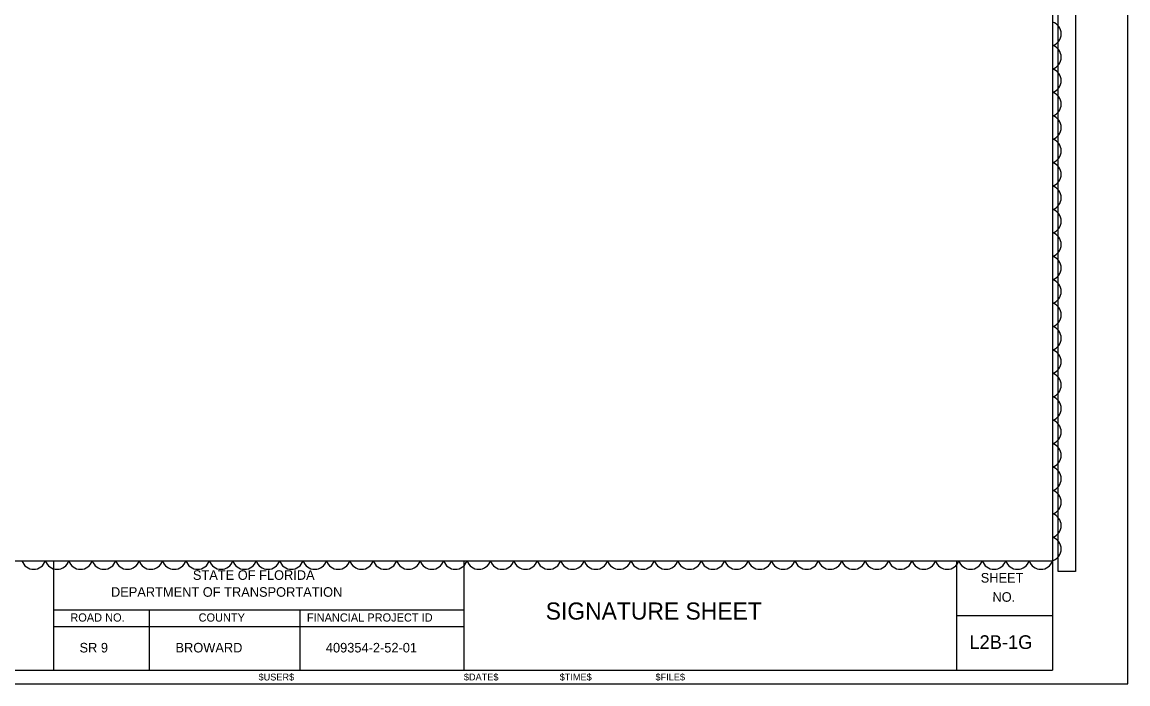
# Model space of a CAD drawing. Extents: x -816.9 to -790.1, y -2199.5 to -2188.9.
# Drawn here: x -802.91 to -794.84, y -2199.5 to -2194.66 of the extents above; entities that cross this region are included whole.
import ezdxf

# ---------------------------------------------------------------- set-up
doc = ezdxf.new("R2010")
doc.units = 0
for name, color, linetype in [('Cloud_dp', 7, 'Continuous'), ('PlotBorder_dp', 7, 'Continuous'), ('ScratchEle_dp', 7, 'Continuous'), ('SheetBorder_dp', 7, 'Continuous'), ('SheetLines_dp', 7, 'Continuous'), ('TextMinor', 7, 'Continuous'), ('TextMisc', 7, 'Continuous'), ('TextShtNo', 7, 'Continuous')]:
    doc.layers.add(name, color=color, linetype=linetype)

msp = doc.modelspace()

# ---------------------------------------------------------------- linework, layer by layer
at = {"layer": 'Cloud_dp'}
for centre, start, end in [((-795.4127, -2194.7504), 287.5, 72.5), ((-795.4127, -2194.9215), 287.5, 72.5), ((-795.4127, -2195.0926), 287.5, 72.5), ((-795.4127, -2195.2638), 287.5, 72.5), ((-795.4127, -2195.4349), 287.5, 72.5), ((-795.4127, -2195.606), 287.5, 72.5), ((-795.4127, -2195.7771), 287.5, 72.5), ((-795.4127, -2195.9482), 287.5, 72.5), ((-795.4127, -2196.1194), 287.5, 72.5), ((-795.4127, -2196.2905), 287.5, 72.5), ((-795.4127, -2196.4616), 287.5, 72.5), ((-795.4127, -2196.6327), 287.5, 72.5), ((-795.4127, -2196.8039), 287.5, 72.5), ((-795.4127, -2196.975), 287.5, 72.5), ((-795.4127, -2197.1461), 287.5, 72.5), ((-795.4127, -2197.3172), 287.5, 72.5), ((-795.4127, -2197.4883), 287.5, 72.5), ((-795.4127, -2197.6595), 287.5, 72.5), ((-795.4127, -2197.8306), 287.5, 72.5), ((-795.4127, -2198.0017), 287.5, 72.5), ((-795.4127, -2198.1728), 287.5, 72.5), ((-795.4127, -2198.344), 287.5, 72.5), ((-795.4127, -2198.5151), 287.5, 72.5), ((-802.8296, -2198.5737), 197.5, 342.5), ((-802.6585, -2198.5737), 197.5, 342.5), ((-802.4874, -2198.5737), 197.5, 342.5), ((-802.3162, -2198.5737), 197.5, 342.5), ((-802.1451, -2198.5737), 197.5, 342.5), ((-801.974, -2198.5737), 197.5, 342.5), ((-801.8029, -2198.5737), 197.5, 342.5), ((-801.6317, -2198.5737), 197.5, 342.5), ((-801.4606, -2198.5737), 197.5, 342.5), ((-801.2895, -2198.5737), 197.5, 342.5), ((-801.1184, -2198.5737), 197.5, 342.5), ((-800.9472, -2198.5737), 197.5, 342.5), ((-800.7761, -2198.5737), 197.5, 342.5), ((-800.605, -2198.5737), 197.5, 342.5), ((-800.4339, -2198.5737), 197.5, 342.5), ((-800.2628, -2198.5737), 197.5, 342.5), ((-800.0916, -2198.5737), 197.5, 342.5), ((-799.9205, -2198.5737), 197.5, 342.5), ((-799.7494, -2198.5737), 197.5, 342.5), ((-799.5783, -2198.5737), 197.5, 342.5), ((-799.4071, -2198.5737), 197.5, 342.5), ((-799.236, -2198.5737), 197.5, 342.5), ((-799.0649, -2198.5737), 197.5, 342.5), ((-798.8938, -2198.5737), 197.5, 342.5), ((-798.7227, -2198.5737), 197.5, 342.5), ((-798.5515, -2198.5737), 197.5, 342.5), ((-798.3804, -2198.5737), 197.5, 342.5), ((-798.2093, -2198.5737), 197.5, 342.5), ((-798.0382, -2198.5737), 197.5, 342.5), ((-797.867, -2198.5737), 197.5, 342.5), ((-797.6959, -2198.5737), 197.5, 342.5), ((-797.5248, -2198.5737), 197.5, 342.5), ((-797.3537, -2198.5737), 197.5, 342.5), ((-797.1826, -2198.5737), 197.5, 342.5), ((-797.0114, -2198.5737), 197.5, 342.5), ((-796.8403, -2198.5737), 197.5, 342.5), ((-796.6692, -2198.5737), 197.5, 342.5), ((-796.4981, -2198.5737), 197.5, 342.5), ((-796.3269, -2198.5737), 197.5, 342.5), ((-796.1558, -2198.5737), 197.5, 342.5), ((-795.9847, -2198.5737), 197.5, 342.5), ((-795.8136, -2198.5737), 197.5, 342.5), ((-795.6425, -2198.5737), 197.5, 342.5), ((-795.4713, -2198.5737), 197.5, 342.5)]:
    msp.add_arc(centre, 0.0897, start, end, dxfattribs=at)
at = {"layer": 'PlotBorder_dp'}
msp.add_lwpolyline([(-811.3358, -2199.5006), (-794.8358, -2199.5006), (-794.8358, -2188.9006), (-811.3358, -2188.9006)], close=True, dxfattribs=at)
at = {"layer": 'ScratchEle_dp'}
msp.add_lwpolyline([(-795.3456, -2191.8382), (-795.218, -2191.8382), (-795.218, -2198.6801), (-795.3456, -2198.6801)], close=True, dxfattribs=at)
at = {"layer": 'SheetBorder_dp'}
for p, q in [((-795.3858, -2189.0006), (-795.3858, -2199.4006)), ((-810.7858, -2198.6006), (-795.3858, -2198.6006)), ((-810.7858, -2199.4006), (-795.3858, -2199.4006))]:
    msp.add_line(p, q, dxfattribs=at)
at = {"layer": 'SheetLines_dp'}
for p, q in [((-802.6858, -2198.6006), (-802.6858, -2199.4006)), ((-799.6858, -2199.4006), (-799.6858, -2198.6006)), ((-796.0858, -2199.4006), (-796.0858, -2198.6006)), ((-802.6858, -2198.9606), (-799.6858, -2198.9606)), ((-801.9858, -2198.9606), (-801.9858, -2199.4006)), ((-800.8858, -2198.9606), (-800.8858, -2199.4006)), ((-796.0858, -2199.0006), (-795.3858, -2199.0006)), ((-802.6858, -2199.0806), (-799.6858, -2199.0806))]:
    msp.add_line(p, q, dxfattribs=at)

# ---------------------------------------------------------------- texts
at = {"layer": 'TextMinor'}
msp.add_text('$USER$', height=0.05, dxfattribs=at).set_placement((-801.1868, -2199.4756))
for s, p in [('$DATE$', (-799.6868, -2199.4756)), ('$TIME$', (-798.9868, -2199.4756)), ('$FILE$', (-798.2868, -2199.4756))]:
    msp.add_text(s, height=0.05, rotation=360, dxfattribs=at).set_placement(p)
at = {"layer": 'TextMisc'}
for s, height, p in [('STATE OF FLORIDA', 0.07, (-801.6664, -2198.7405)), ('DEPARTMENT OF TRANSPORTATION', 0.07, (-802.265, -2198.8641)), ('       SIGNATURE SHEET         ', 0.125, (-799.414, -2199.0309)), ('ROAD NO.', 0.06, (-802.5619, -2199.0455)), ('COUNTY', 0.06, (-801.6248, -2199.0455)), ('FINANCIAL PROJECT ID', 0.06, (-800.8335, -2199.0455)), (' SR 9  ', 0.07, (-802.5207, -2199.271)), ('  BROWARD   ', 0.07, (-801.8455, -2199.271)), ('409354-2-52-01', 0.07, (-800.6951, -2199.271))]:
    msp.add_text(s, height=height, dxfattribs=at).set_placement(p)
for s, p in [('SHEET', (-795.911, -2198.7601)), ('NO.', (-795.8253, -2198.9003))]:
    msp.add_text(s, height=0.07, rotation=359.86066, dxfattribs=at).set_placement(p)
at = {"layer": 'TextShtNo'}
msp.add_text('L2B-1G', height=0.1, dxfattribs=at).set_placement((-795.9941, -2199.2455))

doc.saveas('drawing.dxf')
